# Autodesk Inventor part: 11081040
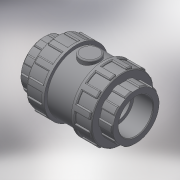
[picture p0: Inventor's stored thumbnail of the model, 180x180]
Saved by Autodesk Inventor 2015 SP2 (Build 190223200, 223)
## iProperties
Created: 2017-11
Part Number: 11081040
Material: Generic
Description: PLASSON CHECK VALVE THR 4" PTFE COATED SPRING + EPDM O-RING
Document SubType Name: Modeling
Designer: KIM
Density: 1 g/cm^3
Appearance: Default
Author: KIM
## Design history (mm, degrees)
derived "110810 - 110610 110910 - 110010.ipt"
feature "Solid1::110810 - 110610 110910 - 110010.ipt"
tag "TaggingFeature1"
body "Solid1"
other parameters: "d0" = 295, "d1" = 110.072, "d2" = 207, "d3" = 61, "d4" = 88.0576, "d5" = 42.7, "d7" = 154.1008, "d8" = 186.3, "d13" = 3.30216, "d23" = 61, "d24" = 198.72, "d25" = 2.20144, "d26" = 3.30216, "d27" = 31.05, "d28" = 15.525, "d29" = 45.75, "d30" = 0, "d35" = 3.30216, "d39" = 103.5, "d45" = 360 deg, "d47" = 2.20144, "d50" = 103.5, "d51" = 62.1, "d53" = 0, "d54" = 4.14, "d55" = 22.0144, "d56" = 11.0072, "d58" = 0, "d59" = 3.30216, "d61" = 360 deg, "G_" = 110.072, "l_" = 61, "H_" = 295, "K_" = 207
